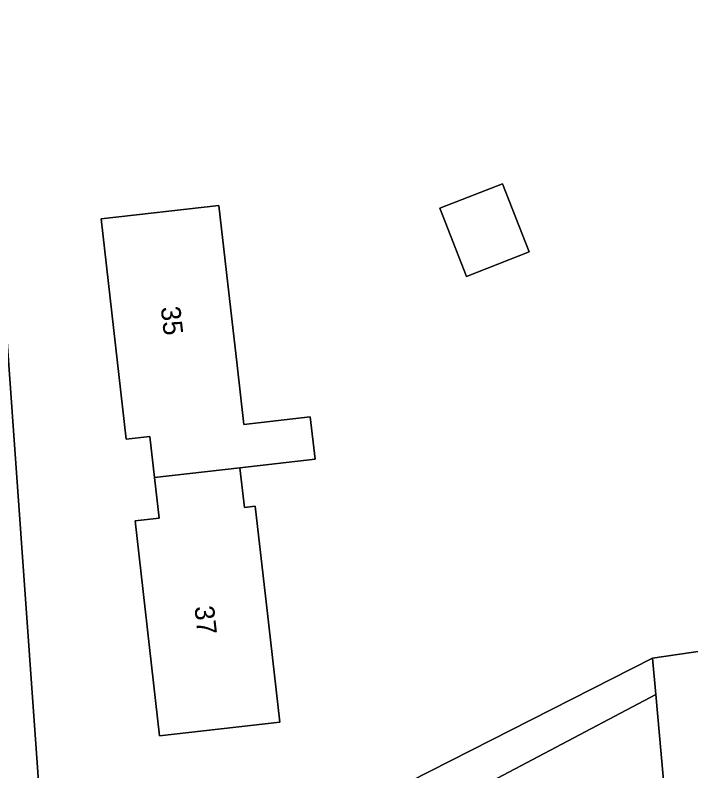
# Model space of a CAD drawing. Extents: x 162661 to 163484, y 380247 to 381230.
# Drawn here: x 163049.68 to 163084.29, y 380463.16 to 380501.86 of the extents above; entities that cross this region are included whole.
import ezdxf

# ---------------------------------------------------------------- set-up
doc = ezdxf.new("R2010")
doc.units = 0
for name, color, linetype in [('IMGEO_Erf', 7, 'Continuous'), ('IMGEO_Groenvoorziening', 7, 'Continuous'), ('IMGEO_Pand', 7, 'Continuous'), ('IMGEO_Pand_nummerreeks', 7, 'Continuous'), ('IMGEO_Rijbaan_lokaal_open', 7, 'Continuous'), ('IMGEO_Voetpad_open', 7, 'Continuous')]:
    doc.layers.add(name, color=color, linetype=linetype)

msp = doc.modelspace()

# ---------------------------------------------------------------- linework, layer by layer
at = {"layer": 'IMGEO_Erf'}
for points in [[(163118.63, 380500), (163117.111, 380515.36), (163116.633, 380519.83), (163113.341, 380519.572), (163077.925, 380516.403), (163076.715, 380524.487), (163046.661, 380521.315), (163048.191, 380500), (163051.286, 380456.864), (163068.185, 380458.61), (163067.852, 380461.575), (163082.32, 380468.935), (163117.508, 380474.084), (163120.943, 380474.451), (163120.425, 380480.773)], [(163076.011, 380489.731), (163072.801, 380488.472), (163071.43, 380491.968), (163074.641, 380493.227)], [(163065.04, 380479.112), (163061.189, 380478.68), (163061.418, 380476.651), (163061.979, 380476.714), (163062.667, 380470.623), (163063.228, 380465.654), (163057.069, 380464.958), (163055.827, 380475.956), (163057.056, 380476.095), (163056.819, 380478.19), (163056.583, 380480.283), (163055.365, 380480.146), (163054.083, 380491.434), (163060.104, 380492.118), (163060.5, 380488.671), (163061.046, 380483.926), (163061.394, 380480.898), (163064.795, 380481.288)]]:
    msp.add_lwpolyline(points, close=True, dxfattribs=at)
at = {"layer": 'IMGEO_Groenvoorziening'}
msp.add_lwpolyline([(163083.594, 380454.84), (163082.489, 380467.065), (163069.853, 380460.403), (163070.39, 380454.553), (163076.683, 380453), (163076.576, 380454.183)], close=True, dxfattribs=at)
at = {"layer": 'IMGEO_Pand'}
for points in [[(163071.43, 380491.968), (163072.801, 380488.472), (163076.011, 380489.731), (163074.641, 380493.227)], [(163060.5, 380488.671), (163060.104, 380492.118), (163054.083, 380491.434), (163055.365, 380480.146), (163056.583, 380480.283), (163056.819, 380478.19), (163061.189, 380478.68), (163065.04, 380479.112), (163064.795, 380481.288), (163061.394, 380480.898), (163061.046, 380483.926)], [(163056.819, 380478.19), (163057.056, 380476.095), (163055.827, 380475.956), (163057.069, 380464.958), (163063.228, 380465.654), (163062.667, 380470.623), (163061.979, 380476.714), (163061.418, 380476.651), (163061.189, 380478.68)]]:
    msp.add_lwpolyline(points, close=True, dxfattribs=at)
at = {"layer": 'IMGEO_Rijbaan_lokaal_open'}
msp.add_lwpolyline([(163087.446, 380466.67), (163117.103, 380470.993), (163119.093, 380471.25), (163117.508, 380474.084), (163082.32, 380468.935), (163082.489, 380467.065), (163083.594, 380454.84), (163083.867, 380451.82), (163090.735, 380452.415), (163119.41, 380454.963), (163120.513, 380455.044), (163120.238, 380458.077), (163118.351, 380457.9), (163088.499, 380455.257)], dxfattribs=at)
at = {"layer": 'IMGEO_Voetpad_open'}
for points in [[(163051.286, 380456.864), (163048.191, 380500), (163046.661, 380521.315), (163076.715, 380524.487), (163076.447, 380526.277), (163046.628, 380523.045), (163042.074, 380586.977), (163070.497, 380590.125)], [(163069.853, 380460.403), (163082.489, 380467.065), (163082.32, 380468.935), (163067.852, 380461.575)]]:
    msp.add_lwpolyline(points, dxfattribs=at)

# ---------------------------------------------------------------- texts
at = {"layer": 'IMGEO_Pand_nummerreeks'}
for s, rotation, p in [('35', 276.4799, (163057.134, 380486.896)), ('37', 276.4431, (163058.86, 380471.561))]:
    msp.add_text(s, height=1, rotation=rotation, dxfattribs=at).set_placement(p)

doc.saveas('drawing.dxf')
